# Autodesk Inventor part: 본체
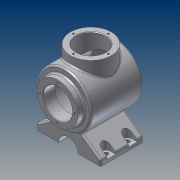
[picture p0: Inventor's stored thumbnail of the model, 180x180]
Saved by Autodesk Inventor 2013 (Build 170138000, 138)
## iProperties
Created: 2017-04
Part Number: 본체
Material: 알루미늄 6061
Document SubType Name: Modeling
Designer: Administrator
Density: 2.71 g/cm^3
Mass: 1670.75 g
Surface Area: 1066.86 cm^2
Volume: 616.514 cm^3
Author: Administrator
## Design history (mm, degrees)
sketch "스케치1"
  geometry: L1 (82, 62)-(82, -58); L2 (109, 62)-(120, 62); L3 (120, 62)-(120, 53); L4 (123, 50)-(129, 50); L5 (132, 47)-(132, -44.454); L6 (109, 62)-(109, 40); L7 (109, 40)-(119, 40); L8 (122, 37)-(122, -37.903); A1 r 113 centre (82, 55) between (82, -58) and (130.282, -47.166); A2 r 103 centre (82, 55) between (82, -48) and (120.11, -40.69); A3 r 3 centre (123, 53) between (120, 53) and (123, 50); A4 r 3 centre (129, 47) between (132, 47) and (129, 50); A5 r 3 centre (119, 37) between (122, 37) and (119, 40); A6 r 3 centre (119, -37.903) between (120.11, -40.69) and (122, -37.903); A7 r 3 centre (129, -44.454) between (130.282, -47.166) and (132, -44.454); 4 further points
  constraints: 16 end point, 16 point on circle, 10 tangent, 7 centre point, 6 point on line, 3 parallel, 3 perpendicular, 2 vertical, 1 horizontal alignment
  dimensions: "d0" = 120 distance of L1.end L1.start; "d3" = 82 distance from line of L1 point (0, 0); "d4" = 54 diameter of L6 L1; "d5" = 76 diameter of L3 L1; "d8" = 100 diameter of L5 L1; "d9" = 22 distance of L2.start L6.end; "d10" = 10 distance between parallel lines of L5 L8; "d11" = 113 radius of A1; "d12" = 10 radial gap between concentric circles of A1 A2; "d13" = 3 radius of A3; "d14" = 3 radius of A4; "d15" = 3 radius of A5; "d16" = 3 radius of A6; "d17" = 3 radius of A7; "d33" = 50 vertical distance of point (0, 0) L4.start; "d109" = 108 distance from line of L1.end L4
revolve "회전1" sketch "스케치1" stored, may be unused: angle "d18" = 90 deg
sketch "스케치2"
  geometry: L1 (60, 0)-(60, 10); L2 (60, 10)-(21.584, 36.899); L3 (-60, 0)-(-60, 10); L4 (-60, 10)-(-21.584, 36.899); L5 (18, 0)-(60, 0); L6 (-60, 0)-(-18, 0); A1 r 50 centre (0, 82) between (21.584, 36.899) and (-21.584, 36.899) reference; A2 r 18 centre (0, 0) between (18, 0) and (-18, 0); 2 further points
  constraints: 12 end point, 5 equal length, 4 point on circle, 2 coincident, 1 centre point, 1 horizontal, 1 perpendicular
  dimensions: "d23" = 36 diameter of A2; "d26" = 60 distance of L3.start point (0, 0); "d27" = 120 distance of L1.start L3.start; "d29" = 55 deg angle of L3 L4; "d30" = 82 vertical distance of A1.centre L3.start; "d102" = 10 distance of L1.end L1.start
extrude "돌출1" join sketch "스케치2" distance "d31" = 42; taper "d32" = 0 deg; dims "d103" = 38, "d104" = 0
node "작업 평면1"
sketch "스케치3"
  geometry: C1 r 38 at (0, 0); 1 further point
  constraints: 1 centre point, 1 coincident
  dimensions: "d35" = 76 diameter of C1
extrude "돌출2" join sketch "스케치3" stored distance "d36" = 80; taper "d37" = 0 deg
hole "구멍1" diameter "d40" = 54; stored, may be unused: countersink angle "d44" = 90 deg, drill point angle "d46" = 118 deg; dims "d38" = 10, "d39" = 10, "d41" = 6, "d42" = 4, "d43" = 2, "d45" = 8
sketch "스케치4"
  geometry: C1 r 38 at (0, 0) reference; 2 further points
  constraints: 1 vertical alignment
  dimensions: "d47" = 32.5 distance of point (0, 32.5) C1.centre
hole "구멍2" sketch "스케치4" at (0, 32.5) diameter "d48" = 3.242; stored, may be unused: countersink angle "d52" = 90 deg, drill point angle "d54" = 118 deg; dims "d49" = 8, "d50" = 4, "d51" = 2, "d53" = 10
sketch "스케치5"
  geometry: C1 r 27 at (0, 0) reference; 1 further point
  constraints: 1 vertical alignment
  dimensions: "d58" = 32.5 distance of point (0, 32.5) C1.centre
hole "구멍3" sketch "스케치5" at (0, 32.5) diameter "d59" = 3.242; stored, may be unused: countersink angle "d63" = 90 deg, drill point angle "d65" = 118 deg; dims "d60" = 8, "d61" = 4, "d62" = 2, "d64" = 10
node "작업 평면2"
sketch "스케치7"
  geometry: L1 (-60, -72)-(-60, -82) reference; C1 r 47 at (0, 0) reference; 2 further points
  constraints: 1 coincident, 1 other
feature "엠보싱1" sketch "스케치7" dims "d69" = 0.5, "d70" = 0
fillet "모깎기1" dims "d71" = 3
chamfer "모따기1" distance "d72" = 1; stored, may be unused: second distance "d73" = 2, angle "d74" = 45 deg
fillet "모깎기2" dims "d75" = 3
fillet "모깎기3" dims "d76" = 3
fillet "모깎기4" dims "d77" = 3
sketch "스케치8"
  geometry: L1 (-78, 77)-(-78, 3) reference; C1 r 4 at (32, 20); C2 r 4 at (-68, 20); C3 r 4 at (-68, 60); C4 r 4 at (32, 60); 4 further points
  constraints: 4 centre point, 3 equal radius, 2 horizontal alignment, 2 vertical alignment
  dimensions: "d78" = 8 diameter of C1; "d82" = 10 horizontal distance of point (42, 3) C1.centre; "d83" = 20 vertical distance of C1.centre point (39, 0); "d105" = 20 vertical distance of point (39, 80) C4.centre; "d106" = 10 horizontal distance of C2.centre L1.end
extrude "돌출3" cut sketch "스케치8" distance "d84" = 6; taper "d85" = 0 deg
sketch "스케치9"
  geometry: L1 (10, 57)-(10, -17) reference; L2 (10, 8)-(0, 8); L3 (0, -8)-(10, -8); L4 (-110.443, 20)-(10, 20); L5 (-68, 60)-(-32, 60) reference; L6 (-32, -20)-(-68, -20) reference; L7 (-50, 60)-(-50, -20); L8 (0, 48)-(10, 48); L9 (10, 32)-(0, 32); L10 (-110, 32)-(-100, 32); L11 (-100, 48)-(-110, 48); L12 (-110, 8)-(-100, 8); L13 (-100, -8)-(-110, -8); L14 (-110, -8)-(-110, 8); L15 (-110, 32)-(-110, 48); L16 (10, -8)-(10, 8); L17 (10, 32)-(10, 48); C1 r 4 at (0, 0) reference; A1 r 8 centre (0, 0) between (0, 8) and (0, -8); A2 r 8 centre (0, 40) between (0, 48) and (0, 32); A3 r 8 centre (-100, 40) between (-100, 32) and (-100, 48); A4 r 8 centre (-100, 0) between (-100, -8) and (-100, 8); 1 further point
  constraints: 28 end point, 15 symmetric about line, 8 point on circle, 4 centre point, 3 collinear, 3 midpoint, 3 perpendicular, 2 point on line, 2 tangent, 1 coincident, 1 horizontal, 3 other
  dimensions: "d86" = 8 radius of A1
extrude "돌출6" cut sketch "스케치9" stored distance "d107" = 10; taper "d108" = 0 deg
node "솔리드1"
pattern_circular "원형 패턴1" dims angle "d56" = 360 deg
pattern_circular "원형 패턴2" dims angle "d67" = 360 deg
other parameters: "d34" = 147, "d98" = 0.5, "d99" = 2, "d100" = 0
